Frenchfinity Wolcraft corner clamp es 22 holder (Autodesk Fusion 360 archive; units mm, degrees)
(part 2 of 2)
mirror "Mirror3" mirrorStitchTolerance 0.1
sketch "filename" plane through (0, 19.6118, 0) normal (0, -1, 0) x axis (1, 0, 0)
  dimension "d216" = 3
sketch "Text" plane through (0, 19.6118, 0) normal (0, -1, 0) x axis (1, 0, 0)
  line L1 (200.5, 60) -> (200.5, 23.2332)
  line L2 (200, 23.2332) -> (200, 60)
  line L3 (200.5, 23.2332) -> (200, 23.2332)
  line L4 (200.5, 60) -> (200.5, 23.2332)
  line L5 (200, 60) -> (200.5, 60)
  line L6 (0, 60) -> (0, 23.2332)
  line L7 (-0.5, 60) -> (0, 60)
  line L8 (-0.5, 23.2332) -> (-0.5, 60)
  line L9 (0, 23.2332) -> (-0.5, 23.2332)
  curve K1
  curve K2
  curve K3
  curve K4
  line L10 (80, 60) -> (40, 60)
  point P4 (200.5, 23.2332)
  point P2 (-0.5, 60)
  coincident P4
  coincident P2
  parallel K3 L10
  dimension "d229" Text1-Height = 3
extrude "Extrude19" cut sketch "Text" against normal blind 2
extrude "Extrude14" cut of existing geometry blind 80 (= "( width_per_slot - width ) / -2")
extrude "Extrude15" cut of existing geometry blind 80 (= "( width_per_slot - width ) / -2")
extrude "Extrude9" cut of existing geometry blind -39 (= "-width_per_slot + 1 mm")
extrude "Extrude10" add of existing geometry blind 199 (= "width - 1 mm")
extrude "Extrude13" cut of existing geometry blind -30
extrude "Extrude14" add of existing geometry blind 80 (= "plate_height")
sketch "Sketch7" plane through (0, 39.6118, 0) normal (0, -1, 0) x axis (1, 0, 0)
  dimension "d236" = 3
extrude "Extrude11" cut sketch "Sketch7" against normal blind 2
sketch "File name" plane through (0, 39.6118, 0) normal (0, -1, 0) x axis (1, 0, 0)
  line L1 (92.897, 7.4163) -> (92.6596, 7.4163)
  line L2 (92.897, 4.404) -> (92.897, 7.4163)
  line L3 (92.5286, 4.404) -> (92.897, 4.404)
  line L4 (92.5286, 6.7512) -> (92.5286, 4.404)
  curve K1 (92.1787, 6.4975) -> (92.5286, 6.7512)
  curve K2 (91.792, 6.3072) -> (92.1787, 6.4975)
  line L5 (91.792, 6.6632) -> (91.792, 6.3072)
  curve K3 (92.3322, 7.0152) -> (91.792, 6.6632)
  curve K4 (92.6596, 7.4163) -> (92.3322, 7.0152)
  line L6 (96.1242, 4.404) -> (96.5641, 6.0759)
  line L7 (95.7394, 4.404) -> (96.1242, 4.404)
  line L8 (95.0744, 6.5773) -> (95.7394, 4.404)
  line L9 (95.455, 6.5773) -> (95.0744, 6.5773)
  line L10 (95.8008, 5.3229) -> (95.455, 6.5773)
  line L11 (95.9297, 4.8563) -> (95.8008, 5.3229)
  curve K5 (96.0423, 5.3044) -> (95.9297, 4.8563)
  line L12 (96.3881, 6.5773) -> (96.0423, 5.3044)
  line L13 (96.7667, 6.5773) -> (96.3881, 6.5773)
  line L14 (97.0921, 5.3167) -> (96.7667, 6.5773)
  line L15 (97.2005, 4.9013) -> (97.0921, 5.3167)
  line L16 (97.3254, 5.3208) -> (97.2005, 4.9013)
  line L17 (97.6978, 6.5773) -> (97.3254, 5.3208)
  line L18 (98.0559, 6.5773) -> (97.6978, 6.5773)
  line L19 (97.3765, 4.404) -> (98.0559, 6.5773)
  line L20 (96.9939, 4.404) -> (97.3765, 4.404)
  line L21 (96.648, 5.7055) -> (96.9939, 4.404)
  line L22 (96.5641, 6.0759) -> (96.648, 5.7055)
  line L23 (94.9311, 5.3044) -> (94.9311, 5.6748)
  line L24 (93.7995, 5.3044) -> (94.9311, 5.3044)
  line L25 (93.7995, 5.6748) -> (93.7995, 5.3044)
  line L26 (94.9311, 5.6748) -> (93.7995, 5.6748)
  line L27 (90.4638, 4.404) -> (91.2865, 6.5773)
  line L28 (90.1201, 4.404) -> (90.4638, 4.404)
  line L29 (89.2933, 6.5773) -> (90.1201, 4.404)
  line L30 (89.6821, 6.5773) -> (89.2933, 6.5773)
  line L31 (90.1487, 5.2758) -> (89.6821, 6.5773)
  curve K6 (90.2879, 4.8379) -> (90.1487, 5.2758)
  curve K7 (90.425, 5.2512) -> (90.2879, 4.8379)
  line L32 (90.9079, 6.5773) -> (90.425, 5.2512)
  line L33 (91.2865, 6.5773) -> (90.9079, 6.5773)
  line L34 (0, 47.1259) -> (200, 47.1259)
  line L35 (0, -40) -> (0, 47.1259)
  line L36 (200, 47.1259) -> (200, -40)
  curve K8
  curve K9
  curve K10
  curve K11
  curve K12 (100.1944, 6.5834) -> (99.9427, 7.1769)
  line L37 (200, -40) -> (0, -40)
  line L38 (100.1985, 4.404) -> (100.1985, 4.758)
  curve K13 (99.9427, 7.1769) -> (99.2592, 7.4163)
  curve K14 (101.5716, 7.4163) -> (101.0273, 7.2403)
  line L39 (98.2156, 4.404) -> (100.1985, 4.404)
  curve K15 (96.1252, 1.9443) -> (95.4744, 1.6455)
  curve K16 (99.074, 1.5862) -> (99.1845, 1.9504)
  curve K17 (98.7425, 1.3488) -> (99.074, 1.5862)
  curve K18 (99.162, 1.0582) -> (98.7425, 1.3488)
  curve K19 (100.1207, 6.2294) -> (100.1944, 6.5834)
  curve K20 (102.296, 7.0377) -> (101.9952, 7.3181)
  curve K21 (102.4823, 6.5916) -> (102.296, 7.0377)
  curve K22 (102.5498, 5.8836) -> (102.4823, 6.5916)
  curve K23 (102.4413, 5.0302) -> (102.5498, 5.8836)
  curve K24 (103.2691, 2.0568) -> (103.1606, 1.2014)
  curve K25 (97.9014, 1.3488) -> (97.4778, 1.0786)
  curve K26 (106.4195, 5.8836) -> (106.7162, 4.6639)
  curve K27 (96.3871, 1.5002) -> (96.5078, 1.0991)
  curve K28 (99.3083, 5.3351) -> (99.8752, 5.8631)
  curve K29 (98.8827, 4.9566) -> (99.3083, 5.3351)
  curve K30 (98.7271, 4.758) -> (98.8827, 4.9566)
  curve K31 (100.7019, 6.7389) -> (100.5935, 5.8836)
  curve K32 (101.0273, 7.2403) -> (100.7019, 6.7389)
  curve K33 (98.2585, 4.6598) -> (98.2156, 4.404)
  curve K34 (98.5, 5.0589) -> (98.2585, 4.6598)
  curve K35 (99.6439, 6.1475) -> (98.983, 5.5132)
  curve K36 (99.8158, 6.5916) -> (99.6439, 6.1475)
  curve K37 (104.1388, -0.3293) -> (104.6832, -0.1533)
  curve K38 (108.8588, 6.7389) -> (108.7503, 5.8836)
  line L40 (92.7752, -1.111) -> (93.1436, -1.111)
  curve K39 (96.0495, 1.6271) -> (96.3871, 1.5002)
  curve K40 (95.7405, 1.5411) -> (96.0495, 1.6271)
  curve K41 (95.5358, 1.3119) -> (95.7405, 1.5411)
  curve K42 (95.4744, 0.9108) -> (95.5358, 1.3119)
  curve K43 (106.528, 6.7389) -> (106.4195, 5.8836)
  curve K44 (98.6637, 6.5098) -> (98.8254, 6.9518)
  curve K45 (98.5778, 7.1932) -> (98.2851, 6.5486)
  curve K46 (99.2592, 7.4163) -> (98.5778, 7.1932)
  curve K47 (102.116, 4.5289) -> (102.4413, 5.0302)
  curve K48 (101.5716, 4.3529) -> (102.116, 4.5289)
  curve K49 (100.8902, 4.6639) -> (101.5716, 4.3529)
  curve K50 (100.5935, 5.8836) -> (100.8902, 4.6639)
  line L41 (100.1985, 4.758) -> (98.7271, 4.758)
  curve K51 (98.983, 5.5132) -> (98.5, 5.0589)
  curve K52 (99.6583, 6.96) -> (99.8158, 6.5916)
  curve K53 (99.251, 7.1114) -> (99.6583, 6.96)
  curve K54 (98.8254, 6.9518) -> (99.251, 7.1114)
  line L42 (98.2851, 6.5486) -> (98.6637, 6.5098)
  curve K55 (99.8752, 5.8631) -> (100.1207, 6.2294)
  curve K56 (103.9025, 7.4163) -> (103.3581, 7.2403)
  curve K57 (104.3261, 7.3181) -> (103.9025, 7.4163)
  curve K58 (104.8131, 6.5916) -> (104.6269, 7.0377)
  curve K59 (104.8806, 5.8836) -> (104.8131, 6.5916)
  curve K60 (107.3977, 4.3529) -> (107.942, 4.5289)
  curve K61 (106.7162, 4.6639) -> (107.3977, 4.3529)
  line L43 (93.1436, -1.111) -> (93.1436, -0.053)
  line L44 (95.4744, -0.2781) -> (95.4744, 0.9108)
  line L45 (95.1061, -0.2781) -> (95.4744, -0.2781)
  curve K62 (98.9451, 2.505) -> (98.3128, 2.7342)
  curve K63 (99.1845, 1.9504) -> (98.9451, 2.505)
  line L46 (93.1108, 1.6128) -> (93.1108, 1.8952)
  curve K64 (101.9952, 7.3181) -> (101.5716, 7.4163)
  line L47 (105.8813, 4.404) -> (105.8813, 4.8235)
  line L48 (105.4618, 4.404) -> (105.8813, 4.404)
  line L49 (105.4618, 4.8235) -> (105.4618, 4.404)
  line L50 (105.8813, 4.8235) -> (105.4618, 4.8235)
  curve K65 (106.8533, 7.2403) -> (106.528, 6.7389)
  curve K66 (107.3977, 7.4163) -> (106.8533, 7.2403)
  curve K67 (107.8213, 7.3181) -> (107.3977, 7.4163)
  curve K68 (108.1221, 7.0377) -> (107.8213, 7.3181)
  curve K69 (108.3083, 6.5916) -> (108.1221, 7.0377)
  curve K70 (108.3759, 5.8836) -> (108.3083, 6.5916)
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  dimension "d239" Text1-Height = 3
sketch "Sketch4" plane through (40, 0, 0) normal (1, 0, 0) x axis (0, 1, 0)
  line L1 (44.7318, 53.9359) -> (48.9918, 53.9359)
  line L2 (44.7318, 45.6759) -> (44.7318, 53.9359)
  line L3 (48.9918, 45.6759) -> (44.7318, 45.6759)
  line L4 (48.9918, 47.1259) -> (48.9918, 45.6759)
  line L5 (55.6118, 47.1259) -> (48.9918, 47.1259)
  line L6 (55.6118, 52.4859) -> (55.6118, 47.1259)
  line L7 (48.9918, 52.4859) -> (55.6118, 52.4859)
  line L8 (48.9918, 53.9359) -> (48.9918, 52.4859)
  circle C1 centre (44.7318, 49.8059) radius 0.85
  point P10 (44.7318, 49.8059)
  midpoint L2 P10
  dimension "d241" diameter C1 = 1.7 (= "filament_hole_width")
extrude "Extrude4" cut sketch "Sketch4" profile of L2 C1 no distance stored
sketch "Sketch15" plane through (-0.5, 0, 0) normal (-1, 0, 0) x axis (0, -1, 0)
  line L1 (-19.6118, 60) -> (-19.6118, 23.2332)
  line L2 (-39.6118, 60) -> (-19.6118, 60)
  line L3 (-39.6118, 52.6059) -> (-39.6118, 60)
  line L4 (-33.1118, 52.6059) -> (-39.6118, 52.6059)
  line L5 (-33.1118, 54.0559) -> (-33.1118, 52.6059)
  line L6 (-28.6118, 54.0559) -> (-33.1118, 54.0559)
  line L7 (-28.6118, 45.5559) -> (-28.6118, 54.0559)
  line L8 (-33.1118, 45.5559) -> (-28.6118, 45.5559)
  line L9 (-33.1118, 47.0059) -> (-33.1118, 45.5559)
  line L10 (-39.6118, 47.0059) -> (-33.1118, 47.0059)
  line L11 (-39.6118, 39.6118) -> (-39.6118, 47.0059)
  line L12 (-22.1725, 22.1725) -> (-39.6118, 39.6118)
  arc A1 centre (-21.1118, 23.2332) radius 1.5 clockwise from (-19.6118, 23.2332) to (-22.1725, 22.1725)
  circle C1 centre (-28.6118, 49.8059) radius 0.85
  point P16 (-28.6118, 49.8059)
  midpoint L7 P16
  dimension "d244" diameter C1 = 1.7 (= "filament_hole_width")
sketch "Sketch9" plane through (200, 0, 0) normal (1, 0, 0) x axis (0, 1, 0)
  line L1 (49.1118, 47.0059) -> (55.6118, 47.0059)
  line L2 (49.1118, 45.5559) -> (49.1118, 47.0059)
  line L3 (44.6118, 45.5559) -> (49.1118, 45.5559)
  line L4 (44.6118, 54.0559) -> (44.6118, 45.5559)
  line L5 (49.1118, 54.0559) -> (44.6118, 54.0559)
  line L6 (49.1118, 52.6059) -> (49.1118, 54.0559)
  line L7 (55.6118, 52.6059) -> (49.1118, 52.6059)
  line L8 (55.6118, 47.0059) -> (55.6118, -40)
  line L9 (39.6118, 60) -> (55.6118, 60)
  line L10 (39.6118, 52.4859) -> (39.6118, 60)
  line L11 (32.9918, 52.4859) -> (39.6118, 52.4859)
  line L12 (32.9918, 53.9359) -> (32.9918, 52.4859)
  line L13 (28.7318, 53.9359) -> (32.9918, 53.9359)
  line L14 (28.7318, 45.6759) -> (28.7318, 53.9359)
  line L15 (32.9918, 45.6759) -> (28.7318, 45.6759)
  line L16 (32.9918, 47.1259) -> (32.9918, 45.6759)
  line L17 (39.6118, 47.1259) -> (32.9918, 47.1259)
  line L18 (55.6118, 60) -> (55.6118, 52.6059)
  line L19 (39.6118, -40) -> (39.6118, 47.1259)
  line L20 (55.6118, -40) -> (39.6118, -40)
  circle C1 centre (28.7318, 49.8059) radius 0.85
  circle C2 centre (44.6118, 49.8059) radius 0.85
  point P20 (28.7318, 49.8059)
  point P21 (44.6118, 49.8059)
  midpoint L14 P20
  midpoint L4 P21
  dimension "d247" diameter C1 = 1.7 (= "filament_hole_width")
  dimension "d250" diameter C2 = 1.7 (= "filament_hole_width")
extrude "Extrude12" cut sketch "Sketch9" profile of L4 L14 C1 C2 no distance stored
sketch "Sketch16" plane through (0, 19.6118, 0) normal (0, -1, 0) x axis (1, 0, 0)
  dimension "d253" = 3
extrude "Extrude22" cut sketch "Sketch16" against normal blind 2
extrude "Extrude23" cut sketch "Sketch15" profile of L7 C1 against normal blind 260 and along normal blind 80
sketch "Sketch17" plane through (0, 19.6118, 0) normal (0, -1, 0) x axis (1, 0, 0)
  dimension "d258" = 3
extrude "Extrude24" cut sketch "Sketch17" against normal blind 2
extrude "Extrude26" cut sketch "Text" against normal blind 2
extrude "Extrude27" cut sketch "Text" against normal blind 2
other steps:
create_component "CreateComponent1"
create_component "CreateComponent2"
create_component "CreateComponent3"
create_component "CreateComponent4"
named bodies: "Wall anchor part", "Base plate with slot", "Wall anchor part (1)", "Wall anchor part (2)", "Wall anchor part (3)", "Wall anchor part (4)"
